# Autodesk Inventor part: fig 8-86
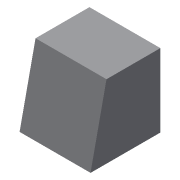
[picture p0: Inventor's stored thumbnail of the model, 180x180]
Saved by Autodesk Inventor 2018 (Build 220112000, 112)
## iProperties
Created: 2009-04
Part Number: fig 8-86
Document SubType Name: Modeling
Designer: Sham
Density: 1 g/cm^3
Material: Generic
Appearance: Default
Author: Sham
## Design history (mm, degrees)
sketch "Sketch5"
  geometry: L1 (14, -14.426)-(0, -14.426); L2 (0, -14.426)-(0, 0); L3 (0, 0)-(14, 0); L4 (14, 0)-(14, -14.426)
  constraints: 8 end point
extrude "Extrusion2" new body sketch "Sketch5" distance "d3" = 20; taper "d4" = 0 deg
sketch "Sketch7"
  geometry: L1 (-2.91, 10)-(18.11, 5.415)
  constraints: 2 end point
split "Split9" sketch "Sketch7"
body "Solid2"
